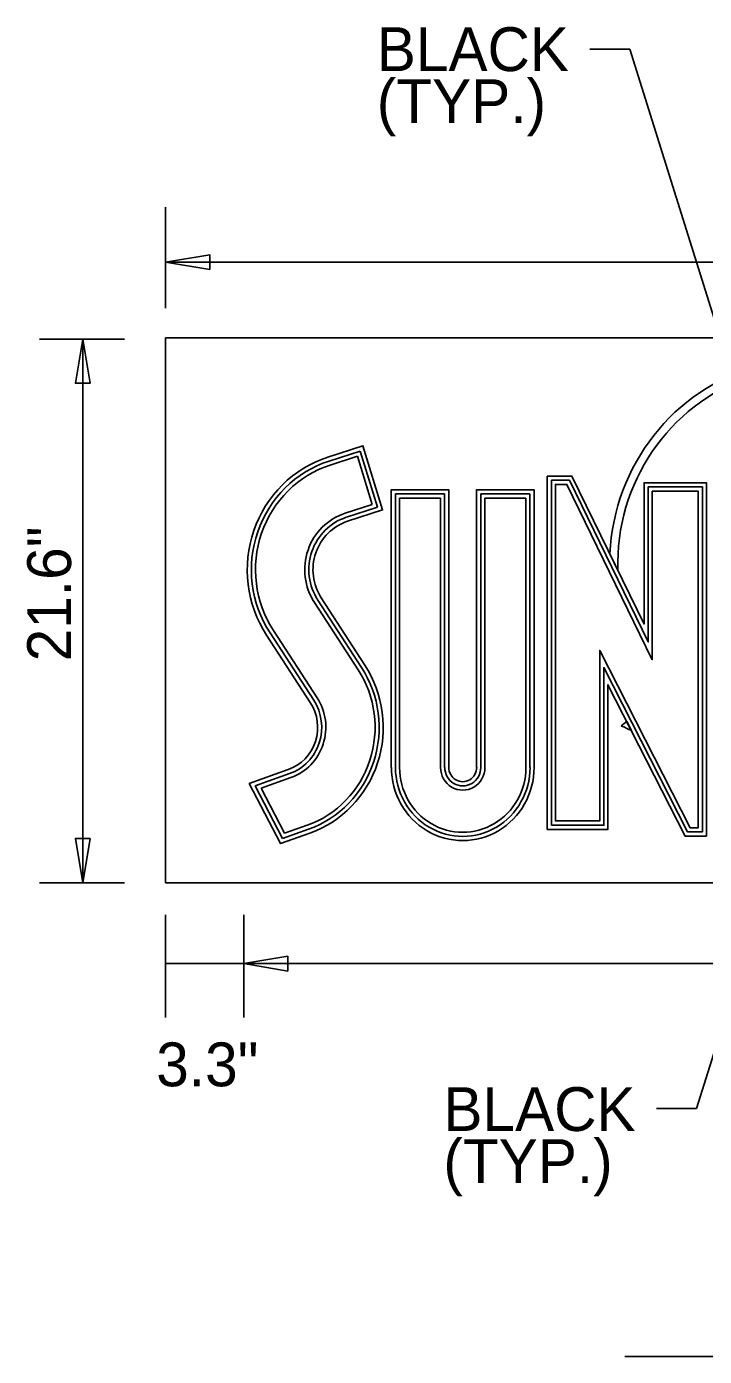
# Model space of a CAD drawing. Extents: x 10268197 to 10268738, y 2141503 to 2142677.
# Drawn here: x 10268624.84 to 10268635.66, y 2142368.15 to 2142389.38 of the extents above; entities that cross this region are included whole.
import ezdxf

# ---------------------------------------------------------------- set-up
doc = ezdxf.new("R2010")
doc.units = 0
for name, color, linetype in [('1', 7, 'Continuous'), ('Default', 7, 'Continuous'), ('GSDims', 7, 'Continuous')]:
    doc.layers.add(name, color=color, linetype=linetype)

msp = doc.modelspace()

# ---------------------------------------------------------------- linework, layer by layer
at = {"layer": '1'}
for p, q in [((10268633.834, 2142389.02), (10268634.473, 2142389.02)), ((10268637.359, 2142379.776), (10268634.473, 2142389.02)), ((10268636.96, 2142376.66), (10268635.538, 2142372.106)), ((10268650.644, 2142375.711), (10268627.057, 2142375.711)), ((10268634.899, 2142372.106), (10268635.538, 2142372.106))]:
    msp.add_line(p, q, dxfattribs=at)
at = {"layer": 'Default'}
for p, q in [((10268629.666, 2142382.443), (10268630.164, 2142382.604)), ((10268630.164, 2142382.604), (10268630.441, 2142381.708)), ((10268629.686, 2142382.379), (10268630.122, 2142382.52)), ((10268629.686, 2142382.379), (10268630.122, 2142382.52)), ((10268630.122, 2142382.52), (10268630.358, 2142381.751)), ((10268630.122, 2142382.52), (10268630.358, 2142381.751)), ((10268633.152, 2142382.205), (10268633.152, 2142376.562)), ((10268633.218, 2142376.63), (10268633.218, 2142382.138)), ((10268633.283, 2142382.071), (10268633.283, 2142376.697)), ((10268633.465, 2142382.071), (10268633.283, 2142382.071)), ((10268634.83, 2142379.271), (10268633.465, 2142382.071)), ((10268634.83, 2142381.963), (10268634.83, 2142379.271)), ((10268635.564, 2142381.963), (10268634.83, 2142381.963)), ((10268635.564, 2142376.589), (10268635.564, 2142381.963)), ((10268630.358, 2142381.751), (10268629.923, 2142381.61)), ((10268630.358, 2142381.751), (10268629.923, 2142381.61)), ((10268630.727, 2142377.552), (10268630.727, 2142381.919)), ((10268630.727, 2142381.919), (10268631.513, 2142381.919)), ((10268630.792, 2142377.552), (10268630.792, 2142381.851)), ((10268630.792, 2142381.851), (10268631.448, 2142381.851)), ((10268630.792, 2142377.552), (10268630.792, 2142381.851)), ((10268630.792, 2142381.851), (10268631.448, 2142381.851)), ((10268631.448, 2142381.851), (10268631.448, 2142377.552)), ((10268631.448, 2142381.851), (10268631.448, 2142377.552)), ((10268631.513, 2142381.919), (10268631.513, 2142377.552)), ((10268632.09, 2142377.552), (10268632.09, 2142381.919)), ((10268632.09, 2142381.919), (10268632.876, 2142381.919)), ((10268632.155, 2142377.552), (10268632.155, 2142381.851)), ((10268632.155, 2142381.851), (10268632.811, 2142381.851)), ((10268632.155, 2142377.552), (10268632.155, 2142381.851)), ((10268632.155, 2142381.851), (10268632.811, 2142381.851)), ((10268632.811, 2142381.851), (10268632.811, 2142377.552)), ((10268632.811, 2142381.851), (10268632.811, 2142377.552)), ((10268632.876, 2142381.919), (10268632.876, 2142377.552)), ((10268630.441, 2142381.708), (10268629.943, 2142381.546)), ((10268634.152, 2142380.962), (10268634.28, 2142380.699)), ((10268630.239, 2142379.187), (10268629.542, 2142380.259)), ((10268629.433, 2142380.184), (10268630.13, 2142379.112)), ((10268629.433, 2142380.184), (10268630.13, 2142379.112)), ((10268629.488, 2142380.222), (10268630.185, 2142379.149)), ((10268628.67, 2142379.663), (10268629.367, 2142378.59)), ((10268629.422, 2142378.628), (10268628.724, 2142379.7)), ((10268629.476, 2142378.665), (10268628.779, 2142379.737)), ((10268629.476, 2142378.665), (10268628.779, 2142379.737)), ((10268633.991, 2142376.697), (10268633.991, 2142379.421)), ((10268633.991, 2142379.421), (10268635.434, 2142376.589)), ((10268634.495, 2142378.141), (10268634.422, 2142378.285)), ((10268628.487, 2142377.257), (10268629.037, 2142377.453)), ((10268628.924, 2142376.417), (10268628.487, 2142377.257)), ((10268628.581, 2142377.22), (10268629.058, 2142377.39)), ((10268628.581, 2142377.22), (10268629.058, 2142377.39)), ((10268628.955, 2142376.5), (10268628.581, 2142377.22)), ((10268628.955, 2142376.5), (10268628.581, 2142377.22)), ((10268629.317, 2142376.629), (10268628.955, 2142376.5)), ((10268629.317, 2142376.629), (10268628.955, 2142376.5)), ((10268633.283, 2142376.697), (10268633.991, 2142376.697)), ((10268629.338, 2142376.565), (10268628.924, 2142376.417)), ((10268635.434, 2142376.589), (10268635.564, 2142376.589)), ((10268650.644, 2142375.711), (10268627.057, 2142375.711)), ((10268634.39, 2142368.148), (10268644.821, 2142368.148))]:
    msp.add_line(p, q, dxfattribs=at)
for points in [[(10268627.057, 2142375.711), (10268627.057, 2142384.409), (10268650.644, 2142384.409), (10268650.644, 2142375.711)], [(10268629.962, 2142381.482), (10268630.523, 2142381.664), (10268630.207, 2142382.689), (10268629.647, 2142382.507)], [(10268633.152, 2142376.562), (10268634.122, 2142376.562), (10268634.122, 2142378.873), (10268635.354, 2142376.455), (10268635.695, 2142376.455), (10268635.695, 2142382.098), (10268634.699, 2142382.098), (10268634.699, 2142379.841), (10268633.546, 2142382.205), (10268633.152, 2142382.205)], [(10268633.218, 2142382.138), (10268633.505, 2142382.138), (10268634.764, 2142379.556), (10268634.764, 2142382.031), (10268635.629, 2142382.031), (10268635.629, 2142376.522), (10268635.394, 2142376.522), (10268634.057, 2142379.147), (10268634.057, 2142376.63), (10268633.218, 2142376.63)], [(10268631.579, 2142377.552), (10268631.579, 2142381.986), (10268630.661, 2142381.986), (10268630.661, 2142377.552)], [(10268632.942, 2142377.552), (10268632.942, 2142381.986), (10268632.024, 2142381.986), (10268632.024, 2142377.552)], [(10268629.015, 2142377.517), (10268628.393, 2142377.295), (10268628.892, 2142376.335), (10268629.36, 2142376.502)]]:
    msp.add_lwpolyline(points, dxfattribs=at)
msp.add_lwpolyline([(10268634.83, 2142381.963), (10268634.83, 2142379.271), (10268633.465, 2142382.071), (10268633.283, 2142382.071), (10268633.283, 2142376.697), (10268633.991, 2142376.697), (10268633.991, 2142379.421), (10268635.434, 2142376.589), (10268635.564, 2142376.589), (10268635.564, 2142381.963)], close=True, dxfattribs=at)
for centre, major_axis, ratio, start_param, end_param in [((10268637.358, 2142380.794), (0, 3.29), 0.97582, 5.303349, 7.802858), ((10268637.358, 2142380.794), (0, 3.29), 0.97582, 5.303349, 7.802858), ((10268637.358, 2142380.794), (0, 3.156), 0.97582, 5.332201, 7.884008), ((10268637.358, 2142380.794), (0, 3.156), 0.97582, 5.332201, 7.884008), ((10268630.201, 2142380.709), (0, 1.886), 0.97582, 0.306207, 2.15869), ((10268630.201, 2142380.709), (0, 1.819), 0.97582, 0.306207, 2.15869), ((10268630.201, 2142380.709), (0, 1.752), 0.975477, 0.305879, 2.158799), ((10268630.201, 2142380.709), (0, 1.752), 0.975477, 0.305879, 2.158799), ((10268630.201, 2142380.709), (0, 0.946), 0.975477, 0.305879, 2.158799), ((10268630.201, 2142380.709), (0, 0.946), 0.975477, 0.305879, 2.158799), ((10268630.201, 2142380.709), (0, 0.878), 0.97582, 0.306207, 2.15869), ((10268630.201, 2142380.709), (0, 0.811), 0.97582, 0.306207, 2.15869), ((10268637.358, 2142380.793), (0, -3.156), 0.97582, 4.712389, 4.712389), ((10268628.785, 2142378.193), (0, 1.791), 0.97582, 3.476656, 5.300276), ((10268628.786, 2142378.193), (0, -1.657), 0.975477, 0.334737, 2.158799), ((10268628.786, 2142378.193), (0, -1.657), 0.975477, 0.334737, 2.158799), ((10268628.785, 2142378.193), (0, 1.724), 0.97582, 3.476656, 5.300276), ((10268628.786, 2142378.193), (0, 0.716), 0.97582, 3.476661, 5.300276), ((10268628.786, 2142378.193), (0, 0.783), 0.97582, 3.476661, 5.300276), ((10268628.786, 2142378.193), (0, -0.85), 0.975477, 0.334742, 2.158799), ((10268628.786, 2142378.193), (0, -0.85), 0.975477, 0.334742, 2.158799), ((10268640.609, 2142369.718), (0, 10.658), 0.97582, 0.637151, 0.647654), ((10268640.609, 2142369.718), (0, 10.658), 0.97582, 0.637152, 0.647654), ((10268628.766, 2142365.835), (0, 13.634), 0.97582, 5.837989, 5.851358), ((10268628.766, 2142365.835), (0, 13.634), 0.97582, 5.837989, 5.851358), ((10268631.802, 2142377.552), (0, 1.168), 0.97582, 1.570446, 4.71274), ((10268631.802, 2142377.552), (0, 1.101), 0.97582, 1.570446, 4.71274), ((10268631.802, 2142377.552), (0, -1.035), 0.975477, 4.712389, 7.853982), ((10268631.802, 2142377.552), (0, -1.035), 0.975477, 4.712389, 7.853982), ((10268631.802, 2142377.552), (0, -0.363), 0.975477, 4.712389, 7.853982), ((10268631.802, 2142377.552), (0, -0.363), 0.975477, 4.712389, 7.853982), ((10268631.802, 2142377.552), (0, 0.295), 0.97582, 1.570446, 4.71274), ((10268631.802, 2142377.552), (0, 0.228), 0.97582, 1.570446, 4.71274)]:
    msp.add_ellipse(centre, major_axis=major_axis, ratio=ratio, start_param=start_param, end_param=end_param, dxfattribs=at)
at = {"layer": 'GSDims'}
for p, q in [((10268627.057, 2142384.887), (10268627.057, 2142386.495)), ((10268627.057, 2142385.621), (10268650.644, 2142385.621)), ((10268626.397, 2142384.391), (10268625.041, 2142384.391)), ((10268625.733, 2142375.711), (10268625.733, 2142384.391)), ((10268626.397, 2142375.711), (10268625.041, 2142375.711)), ((10268627.057, 2142375.197), (10268627.057, 2142373.558)), ((10268628.304, 2142375.197), (10268628.304, 2142373.558)), ((10268627.057, 2142374.419), (10268628.304, 2142374.419)), ((10268628.304, 2142374.419), (10268649.427, 2142374.419))]:
    msp.add_line(p, q, dxfattribs=at)
for points in [[(10268627.057, 2142385.621), (10268627.761, 2142385.503), (10268627.761, 2142385.738)], [(10268625.733, 2142384.391), (10268625.85, 2142383.687), (10268625.615, 2142383.687)], [(10268625.733, 2142375.711), (10268625.85, 2142376.415), (10268625.615, 2142376.415)], [(10268628.304, 2142374.419), (10268629.008, 2142374.536), (10268629.008, 2142374.301)]]:
    msp.add_lwpolyline(points, close=True, dxfattribs=at)

# ---------------------------------------------------------------- texts
at = {"layer": '1'}
for s, p in [('BLACK', (10268630.429, 2142388.67)), ('(TYP.)', (10268630.429, 2142387.839)), ('3.3"', (10268626.906, 2142372.461)), ('BLACK', (10268631.493, 2142371.747)), ('(TYP.)', (10268631.493, 2142370.916))]:
    msp.add_text(s, height=0.7, dxfattribs=at).set_placement(p)
msp.add_text('21.6"', height=0.7, rotation=90, dxfattribs=at).set_placement((10268625.546, 2142379.245))

doc.saveas('drawing.dxf')
